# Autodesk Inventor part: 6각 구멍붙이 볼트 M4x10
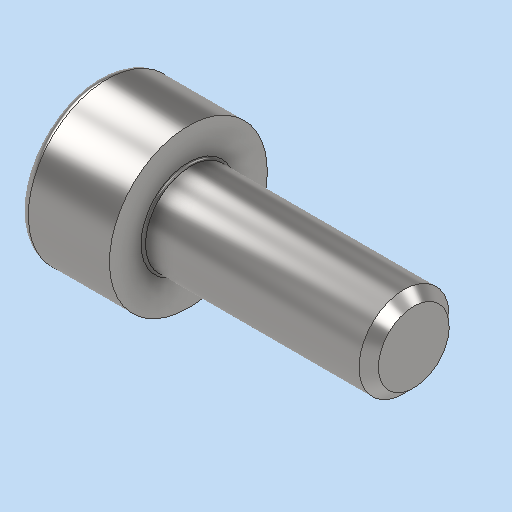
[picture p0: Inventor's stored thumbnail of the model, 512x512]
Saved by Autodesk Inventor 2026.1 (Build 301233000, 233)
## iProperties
Created: 2025-09
Part Number: 6각 구멍붙이 볼트 M4x10
Material: 강철, 연강
Description: 6각머리 태핑 나사
Document SubType Name: Modeling
Designer: PC-30
Density: 7.85 g/cm^3
Appearance: 기본값
Author: jhkim
Sending System: Autodesk Inventor 2026
Preprocessor: ST-DEVELOPER v20.1
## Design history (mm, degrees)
feature "Solid1"
node "솔리드1"
